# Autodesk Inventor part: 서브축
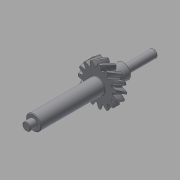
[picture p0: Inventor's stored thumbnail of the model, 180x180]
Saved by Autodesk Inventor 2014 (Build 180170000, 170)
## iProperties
Created: 2016-12
Part Number: 서브축
Material: 강철, 탄소
Document SubType Name: Modeling
Designer: mduedu
Categories: <?xml version="1.0" encoding="UTF-16"?> <MemberInstance><Categories><FamilyTemplate><FamilyTemplateParameter ValueType="xs:double" Id="1" ObjectReferenceKey="da
Density: 7.87 g/cm^3
Appearance: 기본값
Mass: 199.401 g
Surface Area: 86.9137 cm^2
Volume: 25.3368 cm^3
CustomPartVersion: 1
Author: mduedu
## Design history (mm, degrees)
sketch "Sketch1"
  geometry: C1 r 19.321 at (0, 0)
  constraints: 1 centre point
  dimensions: "d0" = 38.64102 diameter of C1 (= da_da)
extrude "Extrusion1" new body sketch "Sketch1" distance "d1" = 10 (= da_b); taper "d2" = 0 deg
workplane "Work Plane2"
sketch "Sketch2"
  geometry: C1 r 19.321 at (0, 0) reference; C2 r 17.321 at (0, 0)
  constraints: 1 centre point, 1 coincident
  dimensions: "d3" = 34.64102 diameter of C2 (= da_dw)
feature "피치 지름" sketch "Sketch2" dims "d4" = 10, "d5" = 0
workplane "Work Plane8"
workplane "Work Plane9"
feature "스퍼 기어" dims "da_b" = 10, "da_d" = 34.64102, "da_aw" = 43.87862, "da_da" = 38.64102, "da_df" = 29.64102, "da_dw" = 34.64102, angle "da_beta" = 30 deg, "da_lefttooth" = 0, "da_righttooth" = 10
sketch "스케치3"
  geometry: C1 r 7.5 at (0, 0); 1 further point
  constraints: 1 centre point, 1 coincident
  dimensions: "d49" = 15 diameter of C1
extrude "돌출2" join sketch "스케치3" distance "d50" = 64; taper "d51" = 0 deg
sketch "스케치4"
  geometry: C1 r 4 at (0, 0); 1 further point
  constraints: 1 centre point, 1 coincident
  dimensions: "d52" = 8 diameter of C1
extrude "돌출3" join sketch "스케치4" distance "d53" = 7; taper "d54" = 0 deg
sketch "스케치5"
  geometry: C1 r 7.5 at (0, 0) reference; 1 further point
extrude "돌출4" join sketch "스케치5" distance "d55" = 16; taper "d56" = 0 deg
sketch "스케치6"
  geometry: C1 r 4 at (0, 0); 1 further point
  constraints: 1 centre point, 1 coincident
  dimensions: "d57" = 8 diameter of C1
extrude "돌출5" join sketch "스케치6" distance "d58" = 30; taper "d59" = 0 deg
chamfer "모따기1" distance "d60" = 0.5; stored, may be unused: second distance "d61" = 2, angle "d62" = 45 deg
fillet "모깎기1" dims "d63" = 0.5
body "Solid1"
body "Srf1"
other parameters: "d16" = 43.87862 (= da_aw), "d17" = 0, "d34" = 12 deg (computed from da_z), "d39" = 0, "d41" = 0, "d43" = 43.87862 (= da_aw), "d46" = 43.87862 (= da_aw), "d47" = 0, "d48" = 0
